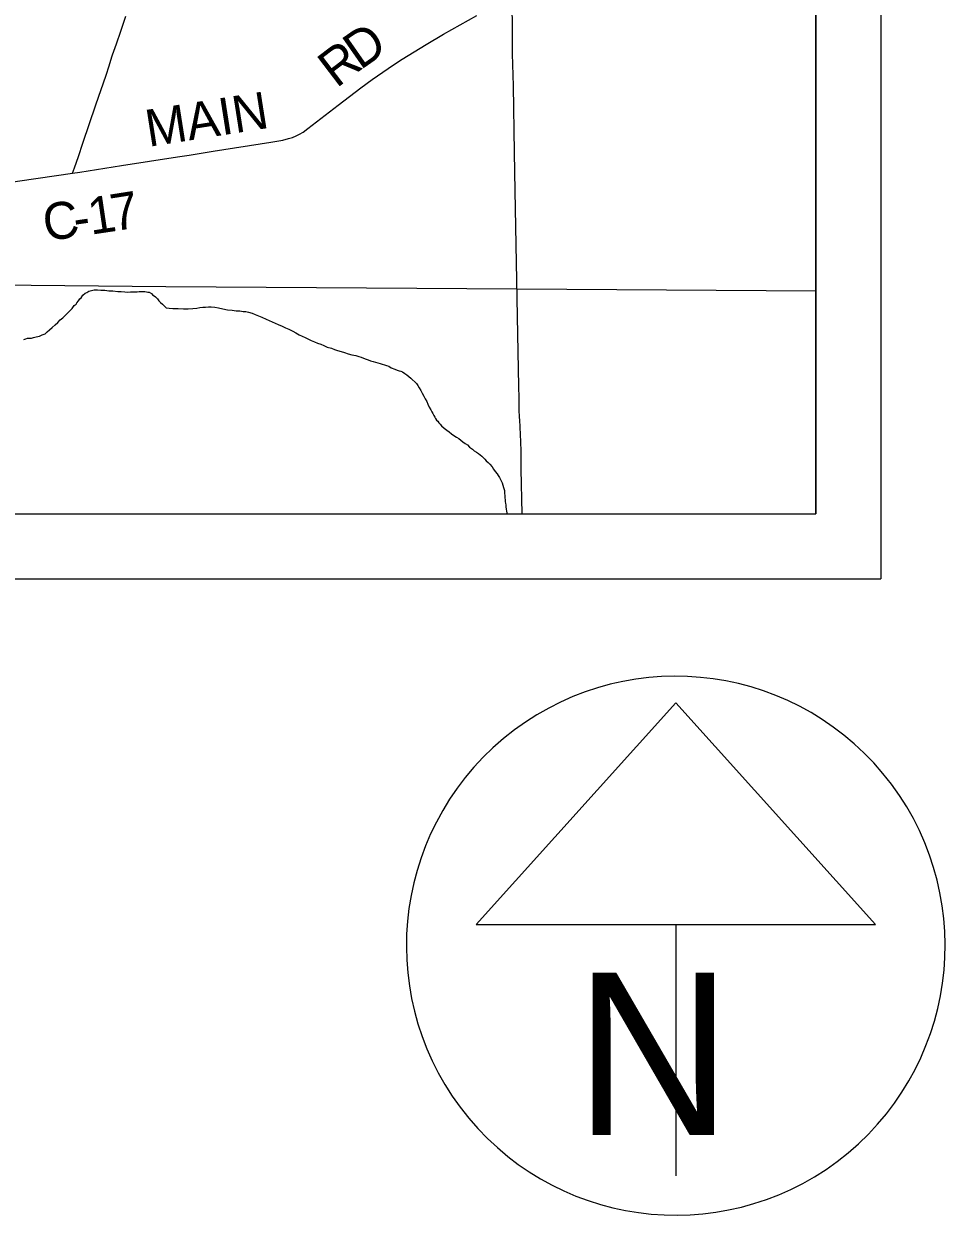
# Model space of a CAD drawing. Extents: x 0 to 34, y 0 to 22.
# Drawn here: x 7.681 to 9.099, y 13.021 to 14.854 of the extents above; entities that cross this region are included whole.
import ezdxf

# ---------------------------------------------------------------- set-up
doc = ezdxf.new("R2010")
doc.units = 0
for name, color, linetype in [('GM_X_Corporation', 7, 'Continuous'), ('GM_X_County_Road', 7, 'Continuous'), ('GM_X_County_Road_Text', 7, 'Continuous'), ('GM_X_Minor_River', 7, 'Continuous'), ('GM_X_Rail_Line', 7, 'Continuous'), ('GM_X_Township_Road', 7, 'Continuous'), ('SH_Data', 7, 'Continuous')]:
    doc.layers.add(name, color=color, linetype=linetype)

msp = doc.modelspace()

# ---------------------------------------------------------------- linework, layer by layer
at = {"layer": 'GM_X_Corporation'}
for points in [[(2.1, 20.7089), (2.1, 14.1), (8.9, 14.1), (8.9, 18.9067)], [(4.4234, 14.8562), (4.4253, 14.7443), (4.427, 14.6635), (4.4269, 14.6591), (4.4274, 14.64), (4.4276, 14.6307), (4.4279, 14.6184), (4.4282, 14.6082), (4.4282, 14.5944), (4.4285, 14.5905), (4.4301, 14.5114), (4.431, 14.4741), (4.4318, 14.4347), (4.4315, 14.4227), (4.4317, 14.396), (4.4325, 14.3733), (4.4327, 14.3684), (4.4332, 14.3373), (4.4348, 14.2876), (4.437, 14.154), (4.4374, 14.1), (8.9, 14.1), (8.9, 16.8293)]]:
    msp.add_lwpolyline(points, dxfattribs=at)
at = {"layer": 'GM_X_County_Road'}
for points in [[(7.7554, 14.6246), (7.7667, 14.6262), (7.8312, 14.6363), (7.9172, 14.6495), (7.9354, 14.6521), (7.972, 14.6583), (8.0611, 14.6722), (8.0793, 14.6754), (8.0883, 14.6776), (8.0941, 14.6795), (8.0998, 14.6819), (8.1053, 14.6846), (8.1105, 14.6878), (8.1181, 14.6931), (8.1648, 14.7293), (8.1994, 14.7558), (8.2169, 14.7687), (8.25, 14.7914), (8.263, 14.7998), (8.3, 14.8225), (8.3268, 14.8383), (8.3783, 14.8673)], [(7.6368, 14.607), (7.6745, 14.6126), (7.7554, 14.6246)]]:
    msp.add_lwpolyline(points, dxfattribs=at)
at = {"layer": 'GM_X_Minor_River'}
for points in [[(7.6804, 14.3687), (7.6838, 14.3695), (7.6865, 14.3703), (7.6922, 14.3707), (7.6956, 14.3715), (7.6998, 14.3723), (7.7047, 14.3735), (7.7089, 14.3754), (7.7134, 14.3774), (7.7164, 14.3801), (7.7202, 14.3832), (7.7243, 14.387), (7.7288, 14.3909), (7.733, 14.3947), (7.7368, 14.3986), (7.7409, 14.402), (7.7443, 14.4055), (7.7477, 14.409), (7.7514, 14.4124), (7.7548, 14.4163), (7.7582, 14.4209), (7.7612, 14.4228), (7.7623, 14.4247), (7.7646, 14.4282), (7.7668, 14.4308), (7.7687, 14.4324), (7.7717, 14.4366), (7.7751, 14.4397), (7.7778, 14.4409), (7.7808, 14.4428), (7.785, 14.444), (7.7887, 14.4448), (7.7941, 14.4448), (7.7994, 14.4445), (7.8055, 14.4442), (7.8116, 14.4435), (7.8177, 14.4432), (7.8253, 14.4425), (7.8306, 14.4422), (7.8359, 14.4418), (7.8405, 14.4415), (7.845, 14.4416), (7.8492, 14.4416), (7.8526, 14.4416), (7.8549, 14.4417), (7.858, 14.4421), (7.8648, 14.4425), (7.8671, 14.4422), (7.8694, 14.4418), (7.8713, 14.4415), (7.8736, 14.4411), (7.877, 14.4392), (7.8789, 14.4373), (7.8812, 14.4359), (7.8835, 14.434), (7.8862, 14.431), (7.8885, 14.4279), (7.8912, 14.4253), (7.8939, 14.423)], [(7.8939, 14.423), (7.8962, 14.4208), (7.8981, 14.4185), (7.9, 14.417), (7.9046, 14.4167), (7.9103, 14.4164), (7.9183, 14.4161), (7.9263, 14.4158), (7.9339, 14.4159), (7.9411, 14.4163), (7.9468, 14.4168), (7.9517, 14.4176), (7.9563, 14.418), (7.9601, 14.4184), (7.965, 14.4185), (7.9692, 14.4185), (7.9745, 14.4182), (7.9802, 14.4171), (7.9871, 14.4157), (7.9943, 14.4142), (8.0012, 14.4135), (8.0076, 14.4128), (8.013, 14.4125), (8.0183, 14.4118), (8.0225, 14.4115), (8.0267, 14.4104), (8.032, 14.4089), (8.0366, 14.407), (8.0419, 14.4048), (8.0473, 14.4026), (8.0538, 14.3996), (8.0725, 14.3914), (8.0782, 14.3888), (8.0836, 14.3866), (8.0885, 14.3844), (8.0946, 14.3814), (8.0992, 14.3788), (8.1046, 14.3758), (8.1092, 14.3736), (8.1137, 14.3713), (8.1187, 14.3691), (8.1233, 14.3669), (8.1282, 14.365), (8.1328, 14.3628), (8.1378, 14.3613), (8.1427, 14.3591), (8.1477, 14.3565), (8.1542, 14.355), (8.1588, 14.3532), (8.1637, 14.3513), (8.1691, 14.3498), (8.1744, 14.3484), (8.1801, 14.3465), (8.1858, 14.3451), (8.1916, 14.3436), (8.1965, 14.3425), (8.2003, 14.341), (8.2034, 14.3399), (8.208, 14.3381), (8.211, 14.337), (8.2144, 14.3355), (8.2183, 14.3344), (8.2221, 14.3337), (8.2255, 14.3325), (8.2293, 14.3314), (8.2324, 14.3307), (8.2358, 14.3296), (8.2392, 14.3285), (8.2427, 14.3274), (8.2465, 14.3248), (8.2518, 14.3229), (8.2556, 14.3215), (8.2587, 14.3203), (8.261, 14.3196), (8.2637, 14.3185), (8.2675, 14.3159), (8.2705, 14.314), (8.2736, 14.3117), (8.2767, 14.3091), (8.2855, 14.3008), (8.2874, 14.2974), (8.2894, 14.294), (8.2917, 14.2899), (8.294, 14.2857), (8.2963, 14.2812), (8.2987, 14.277), (8.301, 14.2728), (8.3029, 14.2687), (8.3049, 14.2641), (8.3072, 14.2604), (8.3087, 14.2573), (8.3103, 14.2543), (8.3118, 14.2517), (8.3134, 14.249), (8.3145, 14.2467), (8.3161, 14.2445), (8.318, 14.2426), (8.3196, 14.2403), (8.3215, 14.2381), (8.3238, 14.2358), (8.328, 14.232)], [(8.328, 14.232), (8.3318, 14.229), (8.3353, 14.2264), (8.3391, 14.2234), (8.3429, 14.2208), (8.3468, 14.2182), (8.3502, 14.2159), (8.3533, 14.2137), (8.3567, 14.211), (8.3602, 14.2084), (8.3636, 14.2062), (8.3667, 14.2028), (8.3713, 14.1998), (8.3743, 14.1971), (8.3778, 14.1949), (8.3808, 14.193), (8.3835, 14.1908), (8.3858, 14.1889), (8.3881, 14.1866), (8.3904, 14.1844), (8.3927, 14.1817), (8.3954, 14.1791), (8.3981, 14.1765), (8.4016, 14.1723), (8.4039, 14.1689), (8.4066, 14.1651), (8.4093, 14.1617), (8.4112, 14.1591), (8.4132, 14.1561), (8.417, 14.1477), (8.4182, 14.1443), (8.4194, 14.1405), (8.4206, 14.136), (8.421, 14.1318), (8.4214, 14.128), (8.4214, 14.1246), (8.4219, 14.1219), (8.4219, 14.1189), (8.4223, 14.1162), (8.4227, 14.1139), (8.4227, 14.1109), (8.4231, 14.1075), (8.4239, 14.1044), (8.4243, 14.1018), (8.4248, 14.1)]]:
    msp.add_lwpolyline(points, dxfattribs=at)
at = {"layer": 'GM_X_Rail_Line'}
msp.add_lwpolyline([(6.9864, 14.5814), (7.029, 14.5989), (7.0627, 14.6057), (7.2079, 14.6065), (7.2345, 14.5949), (7.2447, 14.5804), (7.276, 14.4949), (7.2856, 14.4769), (7.2941, 14.4691), (7.3091, 14.4612), (7.3344, 14.4552), (7.4842, 14.454), (7.8993, 14.4498), (8.4402, 14.4462), (8.9, 14.4434)], dxfattribs=at)
at = {"layer": 'GM_X_Township_Road'}
for points in [[(8.448, 14.1), (8.4462, 14.169), (8.4465, 14.1965), (8.4461, 14.2109), (8.4443, 14.2449), (8.4439, 14.2483), (8.4435, 14.2606), (8.4432, 14.2787), (8.4427, 14.296), (8.4414, 14.3766), (8.4374, 14.5972), (8.4362, 14.6563), (8.4344, 14.7588), (8.4333, 14.8084), (8.4331, 14.855), (8.4328, 14.8767), (8.4325, 14.886), (8.4323, 14.892)], [(7.7554, 14.6246), (7.7584, 14.6325), (7.7649, 14.65), (7.7716, 14.6707), (7.7915, 14.7295), (7.8075, 14.7751), (7.8122, 14.7895), (7.8161, 14.8037), (7.8172, 14.8067), (7.819, 14.8122), (7.8231, 14.8237), (7.8302, 14.843), (7.8378, 14.8664)]]:
    msp.add_lwpolyline(points, dxfattribs=at)
at = {"layer": 'SH_Data'}
for p, q in [((9, 21), (9, 14)), ((8.9, 20.9), (8.9, 14.1)), ((2.1, 14.1), (8.9, 14.1)), ((2, 14), (9, 14)), ((8.6845, 13.8091), (8.3769, 13.4678)), ((8.9921, 13.4678), (8.6845, 13.8091)), ((8.3769, 13.4678), (8.9921, 13.4678)), ((8.6845, 13.4678), (8.6845, 13.0811)), ((8.6845, 13.4353), (8.6845, 13.4353)), ((8.6845, 13.4353), (8.6845, 13.4353))]:
    msp.add_line(p, q, dxfattribs=at)
msp.add_arc((8.6845, 13.4353), 0.4148, 129.7798, 129.7633, dxfattribs=at)

# ---------------------------------------------------------------- texts
at = {"layer": 'GM_X_County_Road_Text'}
for s, height, rotation, p in [('D', 0.0568, 34.8879, (8.1986, 14.7824)), ('R', 0.0568, 37.3476, (8.162, 14.7545)), ('MAIN', 0.05682, 8.9596, (7.8726, 14.6649)), ('C', 0.0568, 8.3349, (7.7143, 14.5195)), ('1', 0.0568, 8.448, (7.7837, 14.5297)), ('7', 0.0568, 8.9467, (7.8188, 14.5349)), ('-', 0.0568, 8.3593, (7.7605, 14.5263))]:
    msp.add_text(s, height=height, rotation=rotation, dxfattribs=at).set_placement(p)
at = {"layer": 'SH_Data'}
msp.add_text('N', height=0.25, dxfattribs=at).set_placement((8.5292, 13.144))

doc.saveas('drawing.dxf')
